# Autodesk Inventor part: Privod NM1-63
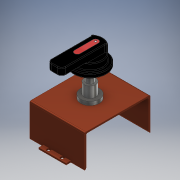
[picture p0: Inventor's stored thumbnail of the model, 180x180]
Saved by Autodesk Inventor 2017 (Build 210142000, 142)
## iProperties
Part Number: Privod NM1-63
Material: Типовые
Document SubType Name: Modeling
Designer: RSagdiev
Density: 1 g/cm^3
Appearance: По умолчанию
Author: RSagdiev
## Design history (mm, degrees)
sketch "Эскиз1"
  geometry: L1 (-19, 52)-(19, 52); L2 (19, 52)-(19, 43.5); L3 (19, 43.5)-(11.5, 43.5); L4 (-19, 43.5)-(-19, 52); L5 (0, 0)-(119.698, 0); L6 (0, 0)-(-104.809, 0); L7 (0, 94.88)-(0, -60.954); L8 (-11.5, 43.5)-(-7.5, 43.5); L9 (-7.5, 43.5)-(-7.5, 48.5); L10 (-9.5, 50.5)-(-9.5, 50.5); L11 (-11.5, 48.5)-(-11.5, 43.5); L12 (7.5, 43.5)-(7.5, 48.5); L13 (9.5, 50.5)-(9.5, 50.5); L14 (11.5, 43.5)-(7.5, 43.5); L15 (11.5, 48.5)-(11.5, 43.5); L16 (-11.5, 43.5)-(-19, 43.5); L17 (-7.5, 43.5)-(-11.5, 43.5); L18 (7.5, 43.5)-(-7.5, 43.5); L19 (11.5, 43.5)-(7.5, 43.5); A1 r 2 centre (-9.5, 48.5) between (-9.5, 50.5) and (-11.5, 48.5); A2 r 2 centre (-9.5, 48.5) between (-7.5, 48.5) and (-9.5, 50.5); A3 r 2 centre (9.5, 48.5) between (9.5, 50.5) and (7.5, 48.5); A4 r 2 centre (9.5, 48.5) between (11.5, 48.5) and (9.5, 50.5); 5 further points
  constraints: 38 end point, 10 point on line, 10 symmetric about line, 8 parallel, 8 point on circle, 4 centre point, 4 horizontal, 4 tangent, 2 perpendicular, 1 concentric, 1 midpoint, 1 vertical, 2 other
  dimensions: "d0" = 43.5 distance between parallel lines of L3 L6 (= 0.5 x Высота); "d1" = 8.5 distance of L1.end L2.end; "d2" = 38 distance between parallel lines of L2 L4 (= 0.5 x Ширина); "d3" = 4 distance of point (-11.5, 50.5) point (-7.5, 50.5); "d4" = 7 distance of point (-7.5, 50.5) L8.end; "d5" = 2 radius of A1 (derived); "d6" = 9.5 distance from line of L4 A1.centre (= 0.25 x d2)
extrude "Выдавливание1" new body sketch "Эскиз1" distance "d7" = 2; taper "d8" = 0 deg
mirror "Зеркальное отражение1"
sketch "Эскиз2"
  geometry: L1 (-19, 52)-(-19, 43.5) reference; L2 (19, 43.5)-(19, 52) reference; L3 (-19, -52)-(-19, -43.5) reference; L4 (19, -43.5)-(19, -52) reference; L5 (-38, 45.5)-(38, 45.5); L6 (38, 45.5)-(38, 43.5); L7 (38, 43.5)-(-38, 43.5); L8 (-38, 43.5)-(-38, 45.5); L9 (-19, 43.5)-(-11.5, 43.5) reference
  constraints: 8 end point, 2 parallel, 1 collinear, 1 horizontal, 1 perpendicular
  dimensions: "d13" = 76 distance of L5.start L5.end (= Ширина); "d14" = 2 distance of L5.end L6.end; "d15" = 19 distance between parallel lines of L1 L8 (= 0.25 x d13)
extrude "Выдавливание2" join sketch "Эскиз2" distance "d11" = 45 (computed from H1); taper "d12" = 0 deg
mirror "Зеркальное отражение2"
sketch "Эскиз3"
  geometry: L1 (-38, 45.5)-(-19, 45.5) reference; L2 (38, -45.5)-(-38, -45.5) reference; L3 (-38, 45.5)-(38, 45.5); L4 (38, 45.5)-(38, -45.5); L5 (38, -45.5)-(-38, -45.5); L6 (-38, -45.5)-(-38, 45.5); 1 further point
  constraints: 8 end point, 2 parallel, 1 horizontal, 1 perpendicular
extrude "Выдавливание3" join sketch "Эскиз3" distance "d16" = 2; taper "d17" = 0 deg
fillet "Сопряжение1" dims "d18" = 2
sketch "Эскиз4"
  geometry: L1 (38, -41.5)-(-38, -41.5) reference; L2 (38, -41.5)-(38, 41.5) reference; L3 (-38, 41.5)-(38, 41.5) reference; L4 (-38, 41.5)-(-38, -41.5) reference; L5 (-38, 41.5)-(-38, -41.5) reference; L6 (-38, -41.5)-(38, 41.5); L7 (38, -41.5)-(38, 41.5) reference; L8 (-38, 41.5)-(38, -41.5); C1 r 5 at (0, 0); 1 further point
  constraints: 4 end point, 1 centre point, 1 coincident
  dimensions: "d19" = 10 diameter of C1
extrude "Выдавливание4" cut sketch "Эскиз4" distance "d20" = 10; taper "d21" = 0 deg
sketch "Эскиз5"
  geometry: C1 r 5 at (0, 0) reference; C2 r 5 at (0, 0); C3 r 8 at (0, 0); 1 further point
  constraints: 2 centre point, 2 coincident
  dimensions: "d22" = 16 diameter of C3
extrude "Выдавливание5" new body sketch "Эскиз5" distance "d23" = 16.33333 (= 0.333333 x H1); taper "d24" = 0 deg
sketch "Эскиз6"
  geometry: C1 r 5 at (0, 0) reference; C2 r 5 at (0, 0); 1 further point
  constraints: 1 centre point, 1 coincident
extrude "Выдавливание6" new body sketch "Эскиз6" distance "d25" = 66.33333 (computed from H1); taper "d26" = 0 deg
sketch "Эскиз7"
  geometry: C1 r 5 at (0, 0) reference; C2 r 13 at (0, 0); C3 r 8 at (0, 0); C4 r 5 at (0, 0); 1 further point
  constraints: 3 centre point, 3 coincident
  dimensions: "d27" = 26 diameter of C2; "d28" = 16 diameter of C3; "d29" = 10 diameter of C4
extrude "Выдавливание7" new body sketch "Эскиз7" distance "d30" = 5; taper "d31" = 0 deg
extrude "Выдавливание8" join sketch "Эскиз7" distance "d32" = 20; taper "d33" = 0 deg
sketch "Эскиз8"
  geometry: C1 r 7 at (0, 0); 1 further point
  constraints: 1 centre point, 1 coincident
  dimensions: "d34" = 14 diameter of C1
extrude "Выдавливание9" new body sketch "Эскиз8" distance "d35" = 3; taper "d36" = 0 deg
fillet "Сопряжение2" dims "d37" = 3
sketch "Эскиз9"
  geometry: L1 (1, 13.17)-(-1, 13.17); L2 (-1, 13.17)-(-1, -13.17); L3 (-1, -13.17)-(1, -13.17); L4 (1, -13.17)-(1, 13.17); L5 (1, 13.17)-(-1, -13.17); L6 (-1, 13.17)-(1, -13.17); L7 (17.109, -1)-(-17.109, -1); L8 (-17.109, -1)-(-17.109, 1); L9 (-17.109, 1)-(17.109, 1); L10 (17.109, 1)-(17.109, -1); L11 (17.109, -1)-(-17.109, 1); L12 (-17.109, -1)-(17.109, 1); C1 r 4 at (0, 0) reference; C2 r 5 at (0, 0) reference; 1 further point
  constraints: 24 end point, 4 midpoint, 4 parallel, 2 horizontal, 2 perpendicular
  dimensions: "d38" = 2 distance of L3.end L2.end; "d39" = 2 distance of L7.end L8.end
extrude "Выдавливание10" cut sketch "Эскиз9" distance "d40" = 1; taper "d41" = 0 deg
sketch "Эскиз10"
  geometry: C1 r 17.5 at (0, 0); A1 r 4 centre (0, 0) between (1, -3.873) and (3.873, -1) reference; 1 further point
  constraints: 1 centre point, 1 coincident
  dimensions: "d42" = 35 diameter of C1
extrude "Выдавливание11" new body sketch "Эскиз10" distance "d43" = 6; taper "d44" = 0 deg; dims "d48" = 3, "d49" = 0
sketch "Эскиз11"
  geometry: C1 r 7 at (0, 0); C2 r 22.5 at (0, 0); 1 further point
  constraints: 2 centre point, 1 coincident
  dimensions: "d45" = 45 diameter of C2
extrude "Выдавливание12" join sketch "Эскиз11" distance "d46" = 6; taper "d47" = 0 deg
sketch "Эскиз12"
  geometry: L1 (-4, -49.361)-(4, -49.361); L2 (10, -43.361)-(10, 10.738); L3 (-10, 10.738)-(-10, -43.361); L4 (-10, -49.361)-(10, 14.361); L5 (10, -49.361)-(-10, 14.361); L6 (-12, 12.738)-(12, 12.738); A1 r 17.5 centre (0, 0) between (10, 14.361) and (0, -17.5) reference; A2 r 17.5 centre (0, 0) between (10, 14.361) and (0, -17.5) reference; A3 r 6 centre (-4, -43.361) between (-10, -43.361) and (-4, -49.361); A4 r 6 centre (4, -43.361) between (4, -49.361) and (10, -43.361); A5 r 2 centre (-12, 10.738) between (-10, 10.738) and (-12, 12.738); A6 r 2 centre (12, 10.738) between (12, 12.738) and (10, 10.738); A7 r 17.5 centre (0, 0) between (12, 12.738) and (-12, 12.738)
  constraints: 16 point on circle, 12 end point, 8 tangent, 6 point on line, 5 centre point, 2 equal radius, 2 horizontal, 2 midpoint, 1 coincident, 1 parallel, 1 perpendicular
  dimensions: "d63" = 20 distance of L4.end L5.end; "d64" = 6 radius of A3; "d66" = 10 distance from line of A1.centre L3; "d67" = 2 radius of A5; "d68" = 2 radius of A6 (derived)
extrude "Выдавливание13" join sketch "Эскиз12" distance "d55" = 10; taper "d56" = 0 deg
fillet "Сопряжение9" dims "d69" = 1
fillet "Сопряжение10" dims "d70" = 1
sketch "Эскиз13"
  geometry: L1 (0, 7.748)-(0, -17.5); L2 (-4, 7.748)-(-4, -17.5); L3 (4, -17.5)-(4, 7.748); A1 r 17.5 centre (0, 0) between (17.5, 0) and (0, -17.5) reference; A2 r 4 centre (0, 7.748) between (4, 7.748) and (-4, 7.748); A3 r 4 centre (0, -17.5) between (-4, -17.5) and (4, -17.5); 2 further points
  constraints: 8 end point, 5 point on circle, 4 tangent, 2 centre point, 1 midpoint, 1 parallel, 1 vertical
  dimensions: "d71" = 8 diameter of A3
extrude "Выдавливание14" cut sketch "Эскиз13" distance "d72" = 0.1; taper "d73" = 0 deg
sketch "Эскиз14"
  geometry: L1 (0, 9.652)-(1.649, 6.796); L2 (1.649, 6.796)-(-1.649, 6.796); L3 (-1.649, 6.796)-(0, 9.652); A1 r 4 centre (0, 7.748) between (4, 7.748) and (-4, 7.748) reference; 2 further points
  constraints: 6 end point, 1 coincident, 7 other
extrude "Выдавливание15" join sketch "Эскиз14" distance "d74" = 0.1; taper "d75" = 0 deg
node "Твердое тело1"
node "Спроецированная петля1"
node "Твердое тело2"
node "Твердое тело3"
node "Твердое тело4"
node "Твердое тело5"
node "Спроецированная петля2"
node "Твердое тело6"
node "Спроецированная петля3"
other parameters: "H1" = 49 [user parameter; used in 3 equation terms], "Высота" = 87 [user parameter; used in 1 equation term], "Ширина" = 76 [user parameter; used in 2 equation terms]
